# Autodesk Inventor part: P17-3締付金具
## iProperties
Created: 2008-07
Part Number: P17-3締付金具
Document SubType Name: Modeling
Designer: y-shimohigashi
Density: 1 g/cm^3
Stock Number: P17-3締付金具
Author: y-shimohigashi
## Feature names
1. 押し出し2 [Extrusion]
2. 押し出し3 [Extrusion]
3. 押し出し6 [Extrusion]
4. 穴4 [Hole]
5. 穴5 [Hole]
6. フィレット4 [Fillet]
